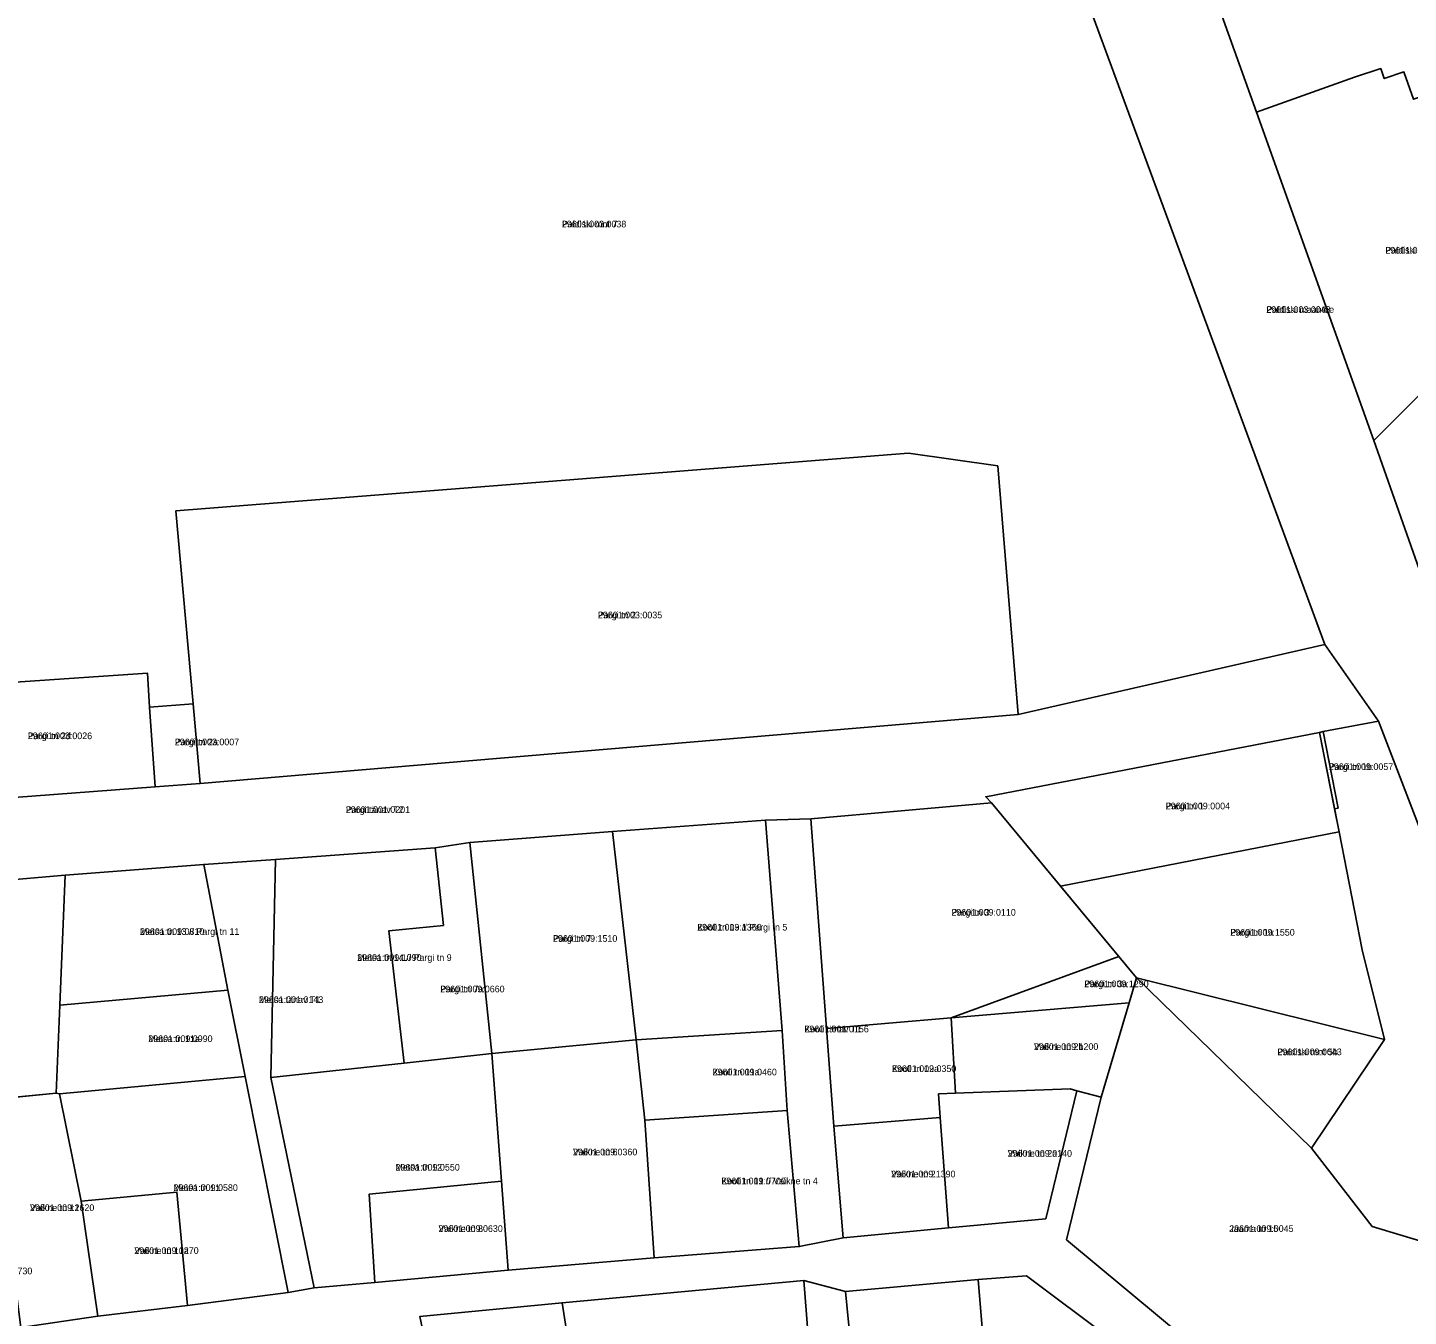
# Model space of a CAD drawing. Extents: x 518839 to 525192, y 6573164 to 6576561.
# Drawn here: x 523365.3 to 523676.7, y 6574666.3 to 6574956.9 of the extents above; entities that cross this region are included whole.
import ezdxf

# ---------------------------------------------------------------- set-up
doc = ezdxf.new("R2010")
doc.units = 0
for name, color, linetype in [('L_AADRESS', 7, 'Continuous'), ('PIIR', 7, 'Continuous'), ('TUNNUS', 7, 'Continuous')]:
    doc.layers.add(name, color=color, linetype=linetype)

msp = doc.modelspace()

# ---------------------------------------------------------------- linework, layer by layer
at = {"layer": 'PIIR'}
for points in [[(523348.5, 6575021.68), (523582.62, 6575021.68), (523657.85, 6574817.75), (523588.65, 6574801.98), (523584.08, 6574858.04), (523563.98, 6574860.91), (523398.79, 6574847.94), (523402.67, 6574804.36), (523392.85, 6574803.66), (523392.34, 6574811.34), (523335.99, 6574807.46), (523333.58, 6574826.12), (523331.51, 6574842.18), (523348.5, 6574887.81), (523348.5, 6574996.68)], [(523682.61, 6575012.28), (523686.03, 6575008.78), (523682.39, 6574993.51), (523693.78, 6574960.27), (523686.54, 6574957.77), (523684.78, 6574957.16), (523685.15, 6574956.02), (523689.39, 6574944.65), (523677.85, 6574940.73), (523675.73, 6574946.66), (523675.65, 6574946.91), (523671.21, 6574945.38), (523670.42, 6574947.65), (523664.49, 6574945.68), (523642.42, 6574937.78), (523627.16, 6574980.41), (523667.65, 6574998.04)], [(523642.42, 6574937.78), (523664.49, 6574945.68), (523670.42, 6574947.65), (523671.21, 6574945.38), (523675.65, 6574946.91), (523675.73, 6574946.66), (523677.85, 6574940.73), (523689.39, 6574944.65), (523690.67, 6574940.81), (523699.12, 6574943.77), (523700.55, 6574939.69), (523695.04, 6574908.44), (523688.8, 6574883.68), (523668.9, 6574863.81)], [(523688.8, 6574883.68), (523701.76, 6574866.77), (523704, 6574867.53), (523712.76, 6574852.4), (523688.32, 6574827.45), (523680.5, 6574830.72), (523668.9, 6574863.81)], [(523398.79, 6574847.94), (523563.98, 6574860.91), (523584.08, 6574858.04), (523588.65, 6574801.98), (523404.23, 6574786.43), (523402.67, 6574804.36)], [(523335.99, 6574807.46), (523392.34, 6574811.34), (523392.85, 6574803.66), (523394.09, 6574785.71), (523339.38, 6574781.51)], [(523404.23, 6574786.43), (523394.09, 6574785.71), (523392.85, 6574803.66), (523402.67, 6574804.36)], [(523657.48, 6574798.12), (523669.94, 6574800.52), (523700.2, 6574721.72), (523689.46, 6574680.22), (523668.48, 6574686.53), (523654.8, 6574704.19), (523671.28, 6574728.73), (523666.25, 6574748.89), (523661.05, 6574775.51), (523660.03, 6574780.73), (523660.82, 6574780.89)], [(523661.05, 6574775.51), (523598.22, 6574763.26), (523582.64, 6574782.07), (523581.36, 6574783.45), (523656.66, 6574797.96)], [(523656.66, 6574797.96), (523657.48, 6574798.12), (523660.82, 6574780.89), (523660.03, 6574780.73)], [(523541.93, 6574778.44), (523582.64, 6574782.07), (523611.37, 6574747.42), (523573.55, 6574733.57), (523545.45, 6574731.19)], [(523497.22, 6574775.63), (523502.57, 6574728.66), (523470.04, 6574725.57), (523465.04, 6574773.11)], [(523497.22, 6574775.63), (523531.75, 6574778.15), (523535.47, 6574730.71), (523502.57, 6574728.66)], [(523535.47, 6574730.71), (523531.75, 6574778.15), (523541.93, 6574778.44), (523545.45, 6574731.19), (523547.1, 6574709.18), (523549.23, 6574683.98), (523539.31, 6574682.01), (523536.63, 6574712.68)], [(523446.75, 6574753.19), (523459.09, 6574754.44), (523457.26, 6574771.89), (523465.04, 6574773.11), (523470.04, 6574725.57), (523450.22, 6574723.39)], [(523661.05, 6574775.51), (523666.25, 6574748.89), (523671.28, 6574728.73), (523615.35, 6574742.57), (523598.22, 6574763.26)], [(523421.21, 6574769.32), (523457.26, 6574771.89), (523459.09, 6574754.44), (523446.75, 6574753.19), (523450.22, 6574723.39), (523420.2, 6574720.1)], [(523373.82, 6574765.75), (523405.05, 6574768.17), (523410.51, 6574739.79), (523372.59, 6574736.41)], [(523410.51, 6574739.79), (523405.05, 6574768.17), (523421.21, 6574769.32), (523420.2, 6574720.1), (523429.95, 6574672.71), (523424.08, 6574671.65), (523414.42, 6574720.36)], [(523326.19, 6574761.62), (523373.82, 6574765.75), (523372.59, 6574736.41), (523371.76, 6574716.56), (523331.45, 6574712.67)], [(523611.37, 6574747.42), (523615.35, 6574742.57), (523613.69, 6574736.97), (523573.55, 6574733.57)], [(523615.35, 6574742.57), (523654.8, 6574704.19), (523668.48, 6574686.53), (523689.46, 6574680.22), (523679.3, 6574630.35), (523672.22, 6574628.03), (523647.77, 6574643.48), (523599.55, 6574683.56), (523607.36, 6574715.71), (523613.69, 6574736.97)], [(523615.35, 6574742.57), (523671.28, 6574728.73), (523654.8, 6574704.19)], [(523371.76, 6574716.56), (523372.59, 6574736.41), (523410.51, 6574739.79), (523414.42, 6574720.36), (523372.55, 6574716.47)], [(523573.55, 6574733.57), (523613.69, 6574736.97), (523607.36, 6574715.71), (523601.91, 6574717.16), (523600.37, 6574717.57), (523574.55, 6574716.59)], [(523545.45, 6574731.19), (523573.55, 6574733.57), (523574.55, 6574716.59), (523570.73, 6574716.44), (523571.13, 6574711.1), (523547.1, 6574709.18)], [(523536.63, 6574712.68), (523504.5, 6574710.5), (523502.57, 6574728.66), (523535.47, 6574730.71)], [(523472.22, 6574696.73), (523470.04, 6574725.57), (523502.57, 6574728.66), (523504.5, 6574710.5), (523506.58, 6574679.43), (523473.73, 6574676.65)], [(523443.6, 6574673.89), (523429.95, 6574672.71), (523420.2, 6574720.1), (523450.22, 6574723.39), (523470.04, 6574725.57), (523472.22, 6574696.73), (523442.36, 6574693.85)], [(523377.4, 6574692.22), (523372.55, 6574716.47), (523414.42, 6574720.36), (523424.08, 6574671.65), (523401.42, 6574668.73), (523399.02, 6574694.31)], [(523371.76, 6574716.56), (523372.55, 6574716.47), (523377.4, 6574692.22), (523381.14, 6574666.32), (523363.81, 6574663.75), (523360.45, 6574690.27), (523354.26, 6574689.99), (523350.61, 6574714.52)], [(523571.13, 6574711.1), (523570.73, 6574716.44), (523574.55, 6574716.59), (523600.37, 6574717.57), (523601.91, 6574717.16), (523594.9, 6574688.29), (523572.99, 6574686.25)], [(523504.5, 6574710.5), (523536.63, 6574712.68), (523539.31, 6574682.01), (523506.58, 6574679.43)], [(523547.1, 6574709.18), (523571.13, 6574711.1), (523572.99, 6574686.25), (523549.23, 6574683.98)], [(523442.36, 6574693.85), (523472.22, 6574696.73), (523473.73, 6574676.65), (523443.6, 6574673.89)], [(523377.4, 6574692.22), (523399.02, 6574694.31), (523401.42, 6574668.73), (523381.14, 6574666.32)], [(523490.79, 6574637.99), (523485.85, 6574669.33), (523540.34, 6574674.35), (523543.19, 6574637.93), (523491.91, 6574630.07)], [(523543.19, 6574637.93), (523540.34, 6574674.35), (523549.77, 6574671.85), (523551.7, 6574651.94), (523552.95, 6574634.06), (523556.48, 6574594.4), (523558.48, 6574567.15), (523560.09, 6574546.96), (523562.38, 6574526.98), (523563.91, 6574507.04), (523565.54, 6574487.01), (523566.98, 6574466.62), (523568.99, 6574441.81), (523569.1, 6574440.03), (523558.83, 6574443.32), (523557.1, 6574466.25), (523554.58, 6574498.15), (523552.58, 6574520.23), (523551.05, 6574542.17), (523548.62, 6574570.34), (523546.53, 6574594.73), (523544.14, 6574614.8)], [(523549.77, 6574671.85), (523579.65, 6574674.61), (523581.29, 6574654.66), (523551.7, 6574651.94)], [(523579.65, 6574674.61), (523590.58, 6574675.41), (523609.74, 6574661.03), (523592.83, 6574639.23), (523586.78, 6574647.32), (523581.29, 6574654.66)], [(523485.85, 6574669.33), (523490.79, 6574637.99), (523461.21, 6574631.85), (523440.01, 6574627.45), (523438.68, 6574632.46), (523459.85, 6574637.41), (523453.75, 6574666.2)]]:
    msp.add_lwpolyline(points, close=True, dxfattribs=at)
for points in [[(523700.2, 6574721.72), (523669.94, 6574800.52), (523657.85, 6574817.75), (523582.62, 6575021.68)], [(523627.16, 6574980.41), (523642.42, 6574937.78), (523668.9, 6574863.81), (523680.5, 6574830.72)], [(523339.38, 6574781.51), (523394.09, 6574785.71), (523404.23, 6574786.43), (523588.65, 6574801.98), (523657.85, 6574817.75), (523669.94, 6574800.52), (523657.48, 6574798.12), (523656.66, 6574797.96), (523581.36, 6574783.45), (523582.64, 6574782.07), (523541.93, 6574778.44), (523531.75, 6574778.15), (523497.22, 6574775.63), (523465.04, 6574773.11), (523457.26, 6574771.89), (523421.21, 6574769.32), (523405.05, 6574768.17), (523373.82, 6574765.75), (523326.19, 6574761.62)], [(523363.81, 6574663.75), (523381.14, 6574666.32), (523401.42, 6574668.73), (523424.08, 6574671.65), (523429.95, 6574672.71), (523443.6, 6574673.89), (523473.73, 6574676.65), (523506.58, 6574679.43), (523539.31, 6574682.01), (523549.23, 6574683.98), (523572.99, 6574686.25), (523594.9, 6574688.29), (523601.91, 6574717.16), (523607.36, 6574715.71), (523599.55, 6574683.56), (523647.77, 6574643.48)], [(523609.74, 6574661.03), (523590.58, 6574675.41), (523579.65, 6574674.61), (523549.77, 6574671.85), (523540.34, 6574674.35), (523485.85, 6574669.33), (523453.75, 6574666.2)]]:
    msp.add_lwpolyline(points, dxfattribs=at)

# ---------------------------------------------------------------- texts
at = {"layer": 'L_AADRESS'}
for s, p in [('Paldiski mnt 7', (523485.82, 6574911.83)), ('Paldiski mnt 26a', (523671.48, 6574905.93)), ('Paldiski maantee', (523644.64, 6574892.56)), ('Pargi tn 2', (523493.92, 6574823.67)), ('Pargi tn 2d', (523365.39, 6574796.43)), ('Pargi tn 2a', (523398.54, 6574795.05)), ('Pargi tn 1b', (523658.74, 6574789.47)), ('Pargi tn 1', (523621.95, 6574780.61)), ('Pargi tänav T2', (523437.08, 6574779.79)), ('Pargi tn 3', (523573.64, 6574756.63)), ('Metsa tn 13 // Pargi tn 11', (523390.68, 6574752.29)), ('Kooli tn 13 // Pargi tn 5', (523516.34, 6574753.27)), ('Pargi tn 7', (523483.8, 6574750.73)), ('Pargi tn 1a', (523636.53, 6574752.12)), ('Metsa tn 14 // Pargi tn 9', (523439.65, 6574746.43)), ('Pargi tn 3a', (523603.6, 6574740.5)), ('Metsa tänav T1', (523417.5, 6574736.94)), ('Pargi tn 7a', (523458.39, 6574739.33)), ('Metsa tn 11a', (523392.55, 6574728.13)), ('Kooli tänav T1', (523540.49, 6574730.32)), ('Vaikne tn 2b', (523592.25, 6574726.34)), ('Paldiski mnt 5b', (523647.14, 6574725.16)), ('Kooli tn 12a', (523560.23, 6574721.38)), ('Kooli tn 11a', (523519.77, 6574720.61)), ('Vaikne tn 6', (523488.31, 6574702.59)), ('Vaikne tn 2a', (523586.32, 6574702.26)), ('Metsa tn 12', (523448.28, 6574699.14)), ('Vaikne tn 2', (523560.05, 6574697.61)), ('Metsa tn 11', (523398.24, 6574694.54)), ('Kooli tn 11 // Vaikne tn 4', (523521.77, 6574696.05)), ('Vaikne tn 12', (523365.88, 6574690.02)), ('Vaikne tn 8', (523457.98, 6574685.31)), ('Jaama tn 15', (523636.27, 6574685.3)), ('Vaikne tn 10a', (523389.41, 6574680.34))]:
    msp.add_text(s, height=1.5, dxfattribs=at).set_placement(p)
at = {"layer": 'TUNNUS'}
for s, p in [('29601:003:0038', (523485.82, 6574911.83)), ('29601:004:0038', (523671.48, 6574905.93)), ('29601:003:0043', (523644.64, 6574892.56)), ('29601:003:0035', (523493.92, 6574823.67)), ('29601:003:0026', (523365.39, 6574796.43)), ('29601:003:0007', (523398.54, 6574795.05)), ('29601:009:0057', (523658.74, 6574789.47)), ('29601:009:0004', (523621.95, 6574780.61)), ('29601:001:0201', (523437.08, 6574779.79)), ('29601:009:0110', (523573.64, 6574756.63)), ('29601:009:0810', (523390.68, 6574752.29)), ('29601:009:1360', (523516.34, 6574753.27)), ('29601:009:1510', (523483.8, 6574750.73)), ('29601:009:1550', (523636.53, 6574752.12)), ('29601:009:1090', (523439.65, 6574746.43)), ('29601:009:1290', (523603.6, 6574740.5)), ('29601:001:0143', (523417.5, 6574736.94)), ('29601:009:0660', (523458.39, 6574739.33)), ('29601:009:0990', (523392.55, 6574728.13)), ('29601:001:0156', (523540.49, 6574730.32)), ('29601:009:1200', (523592.25, 6574726.34)), ('29601:009:0043', (523647.14, 6574725.16)), ('29601:009:0350', (523560.23, 6574721.38)), ('29601:009:0460', (523519.77, 6574720.61)), ('29601:009:0360', (523488.31, 6574702.59)), ('29601:009:0140', (523586.32, 6574702.26)), ('29601:009:0550', (523448.28, 6574699.14)), ('29601:009:1390', (523560.05, 6574697.61)), ('29601:009:0580', (523398.24, 6574694.54)), ('29601:009:0700', (523521.77, 6574696.05)), ('29601:009:1620', (523365.88, 6574690.02)), ('29601:009:0630', (523457.98, 6574685.31)), ('29601:009:0045', (523636.27, 6574685.3)), ('29601:009:1270', (523389.41, 6574680.34)), ('29601:009:1730', (523351.9, 6574675.75))]:
    msp.add_text(s, height=1.5, dxfattribs=at).set_placement(p)

doc.saveas('drawing.dxf')
